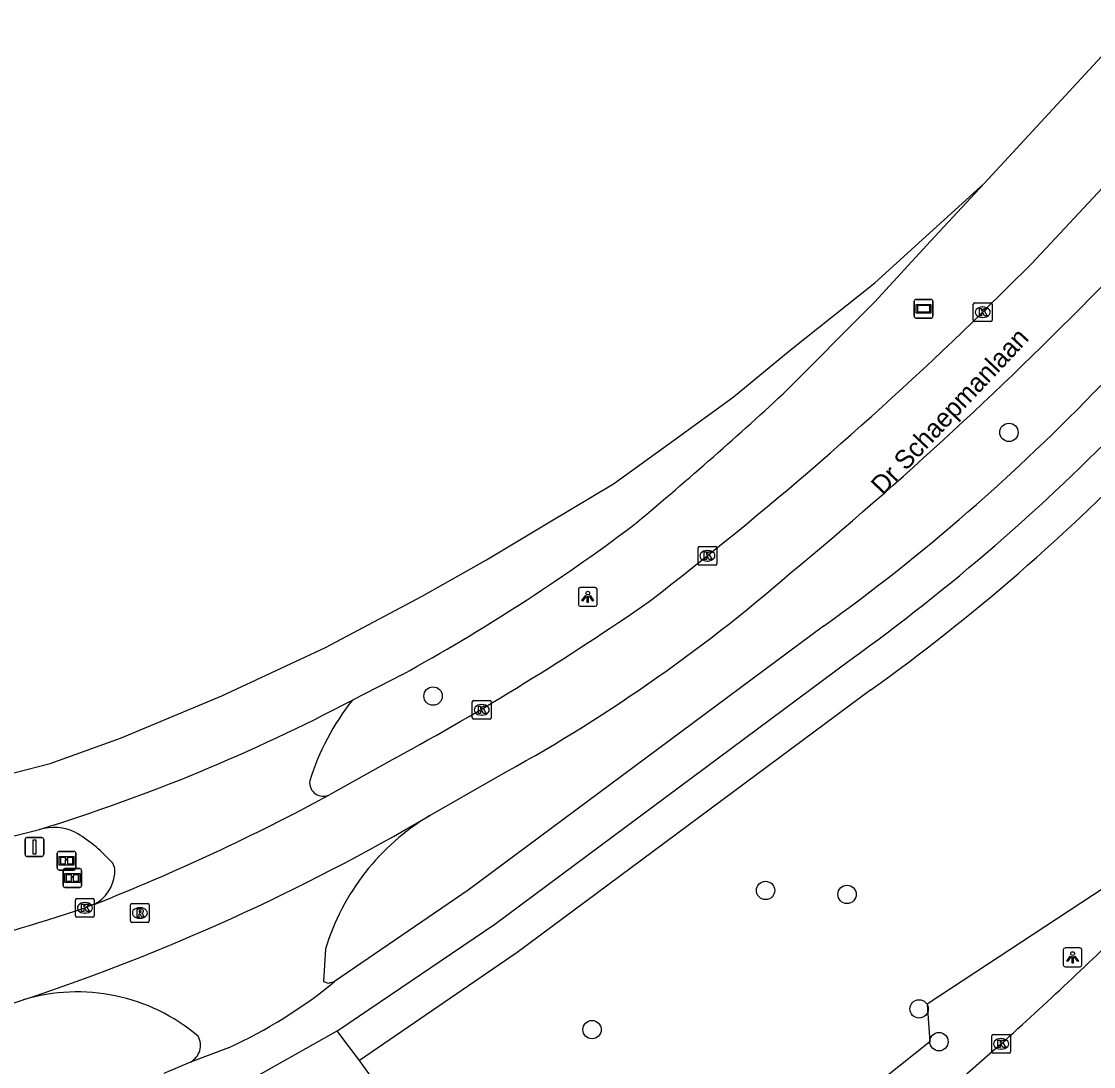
# Model space of a CAD drawing. Extents: x 161402 to 161933, y 381650 to 382313.
# Drawn here: x 161630.3 to 161687.4, y 382149.7 to 382205.3 of the extents above; entities that cross this region are included whole.
import ezdxf

# ---------------------------------------------------------------- set-up
doc = ezdxf.new("R2010")
doc.units = 0
for name, color, linetype in [('IMGEO_Boom', 7, 'Continuous'), ('IMGEO_Fietspad_open', 7, 'Continuous'), ('IMGEO_Groenvoorziening', 7, 'Continuous'), ('IMGEO_Informatiebord', 7, 'Continuous'), ('IMGEO_Kolk', 7, 'Continuous'), ('IMGEO_Lichtpunt', 7, 'Continuous'), ('IMGEO_Openbare_ruimte_label', 7, 'Continuous'), ('IMGEO_Reclamebord', 7, 'Continuous'), ('IMGEO_Rijbaan_lokaal_gesloten', 7, 'Continuous'), ('IMGEO_Rijbaan_lokaal_open', 7, 'Continuous'), ('IMGEO_Rioolput', 7, 'Continuous'), ('IMGEO_Verkeersbordpaal', 7, 'Continuous'), ('IMGEO_Voetpad_open', 7, 'Continuous')]:
    doc.layers.add(name, color=color, linetype=linetype)

msp = doc.modelspace()

# ---------------------------------------------------------------- linework, layer by layer
at = {"layer": 'IMGEO_Boom'}
for centre in [(161682.85, 382183.401), (161652.204, 382169.365), (161669.896, 382159.022), (161674.234, 382158.814), (161678.071, 382152.722), (161660.661, 382151.616), (161679.127, 382150.976)]:
    msp.add_circle(centre, 0.489, dxfattribs=at)
at = {"layer": 'IMGEO_Fietspad_open'}
for points in [[(161672.989, 382173.086), (161654.067, 382159.041), (161646.957, 382154.172)], [(161647.103, 382151.551), (161647.127, 382151.564), (161655.489, 382157.231), (161674.382, 382171.277)], [(161639.289, 382149.891), (161637.879, 382149.285)]]:
    msp.add_lwpolyline(points, dxfattribs=at)
for centre, radius, start, end in [((161610.052, 382260.44), 107.665, 305.77231, 316.20072), ((161609.744, 382261.017), 110.596, 305.76448, 315.97187)]:
    msp.add_arc(centre, radius, start, end, dxfattribs=at)
at = {"layer": 'IMGEO_Groenvoorziening'}
msp.add_lwpolyline([(161703.606, 382170.992), (161702.903, 382171.726), (161702.299, 382171.22), (161695.415, 382165.448), (161687.926, 382159.17), (161678.507, 382152.98), (161678.638, 382150.976), (161676.296, 382149.1), (161669.4, 382148.169), (161664.367, 382144.903), (161668.17, 382139.043)], dxfattribs=at)
at = {"layer": 'IMGEO_Informatiebord'}
for p, q in [((161632.199, 382160.205), (161632.199, 382161.005)), ((161632.199, 382161.005), (161632.199, 382160.205)), ((161632.299, 382161.105), (161633.089, 382161.105)), ((161633.089, 382161.105), (161632.299, 382161.105)), ((161633.189, 382161.005), (161633.189, 382160.205)), ((161633.189, 382160.205), (161633.189, 382161.005)), ((161633.089, 382160.105), (161632.299, 382160.105)), ((161632.299, 382160.105), (161633.089, 382160.105)), ((161632.508, 382159.285), (161632.508, 382160.085)), ((161632.508, 382160.085), (161632.508, 382159.285)), ((161632.608, 382160.185), (161633.398, 382160.185)), ((161633.398, 382160.185), (161632.608, 382160.185)), ((161633.498, 382160.085), (161633.498, 382159.285)), ((161633.498, 382159.285), (161633.498, 382160.085)), ((161633.398, 382159.185), (161632.608, 382159.185)), ((161632.608, 382159.185), (161633.398, 382159.185))]:
    msp.add_line(p, q, dxfattribs=at)
for points in [[(161632.3, 382160.837), (161633.088, 382160.837), (161633.088, 382160.373), (161632.3, 382160.373), (161632.3, 382160.837)], [(161632.365, 382160.772), (161632.365, 382160.438), (161632.64, 382160.438), (161632.641, 382160.651), (161632.745, 382160.652), (161632.746, 382160.438), (161633.023, 382160.438), (161633.023, 382160.772), (161632.747, 382160.772), (161632.747, 382160.692), (161632.641, 382160.692), (161632.641, 382160.772), (161632.365, 382160.772)], [(161632.609, 382159.917), (161633.397, 382159.917), (161633.397, 382159.453), (161632.609, 382159.453), (161632.609, 382159.917)], [(161632.674, 382159.852), (161632.674, 382159.518), (161632.949, 382159.518), (161632.95, 382159.731), (161633.054, 382159.732), (161633.055, 382159.518), (161633.332, 382159.518), (161633.332, 382159.852), (161633.056, 382159.852), (161633.056, 382159.772), (161632.95, 382159.772), (161632.95, 382159.852), (161632.674, 382159.852)]]:
    msp.add_lwpolyline(points, dxfattribs=at)
for centre, start, end in [((161632.299, 382161.005), 90, 180), ((161632.299, 382161.005), 90, 180), ((161633.089, 382161.005), 0, 90), ((161633.089, 382161.005), 360, 90), ((161632.299, 382160.205), 180, 270), ((161632.299, 382160.205), 180, 270), ((161632.608, 382160.085), 90, 180), ((161632.608, 382160.085), 90, 180), ((161633.089, 382160.205), 270, 0), ((161633.089, 382160.205), 270, 0), ((161633.398, 382160.085), 0, 90), ((161633.398, 382160.085), 360, 90), ((161632.608, 382159.285), 180, 270), ((161632.608, 382159.285), 180, 270), ((161633.398, 382159.285), 270, 0), ((161633.398, 382159.285), 270, 0)]:
    msp.add_arc(centre, 0.1, start, end, dxfattribs=at)
at = {"layer": 'IMGEO_Kolk'}
for p, q in [((161680.954, 382189.368), (161680.954, 382190.22)), ((161681.029, 382190.294), (161681.881, 382190.294)), ((161681.442, 382190.074), (161681.467, 382190.074)), ((161681.955, 382190.22), (161681.955, 382189.368)), ((161681.881, 382189.294), (161681.029, 382189.294)), ((161681.465, 382189.514), (161681.44, 382189.514)), ((161666.303, 382176.409), (161666.303, 382177.261)), ((161666.378, 382177.335), (161667.23, 382177.335)), ((161667.304, 382177.261), (161667.304, 382176.409)), ((161666.791, 382177.115), (161666.816, 382177.115)), ((161667.23, 382176.335), (161666.378, 382176.335)), ((161666.814, 382176.555), (161666.789, 382176.555)), ((161654.29, 382168.208), (161654.29, 382169.06)), ((161654.365, 382169.134), (161655.217, 382169.134)), ((161654.778, 382168.914), (161654.803, 382168.914)), ((161655.291, 382169.06), (161655.291, 382168.208)), ((161655.217, 382168.134), (161654.365, 382168.134)), ((161654.801, 382168.354), (161654.776, 382168.354)), ((161633.169, 382157.672), (161633.169, 382158.524)), ((161633.244, 382158.598), (161634.096, 382158.598)), ((161633.657, 382158.378), (161633.682, 382158.378)), ((161634.17, 382158.524), (161634.17, 382157.672)), ((161633.68, 382157.818), (161633.655, 382157.818)), ((161634.096, 382157.598), (161633.244, 382157.598)), ((161681.935, 382150.433), (161681.935, 382151.285)), ((161682.01, 382151.359), (161682.862, 382151.359)), ((161682.423, 382151.139), (161682.448, 382151.139)), ((161682.936, 382151.285), (161682.936, 382150.433)), ((161682.446, 382150.579), (161682.421, 382150.579)), ((161682.862, 382150.359), (161682.01, 382150.359))]:
    msp.add_line(p, q, dxfattribs=at)
for points in [[(161680.954, 382189.368), (161680.954, 382190.22)], [(161681.029, 382190.294), (161681.881, 382190.294)], [(161681.275, 382189.994), (161681.398, 382189.994), (161681.398, 382189.843), (161681.528, 382189.994), (161681.692, 382189.994), (161681.546, 382189.843), (161681.699, 382189.594), (161681.547, 382189.594), (161681.462, 382189.758), (161681.398, 382189.691), (161681.398, 382189.594), (161681.275, 382189.594), (161681.275, 382189.994)], [(161681.955, 382190.22), (161681.955, 382189.368)], [(161681.881, 382189.294), (161681.029, 382189.294)], [(161666.303, 382176.409), (161666.303, 382177.261)], [(161666.378, 382177.335), (161667.23, 382177.335)], [(161667.304, 382177.261), (161667.304, 382176.409)], [(161666.624, 382177.035), (161666.747, 382177.035), (161666.747, 382176.884), (161666.877, 382177.035), (161667.041, 382177.035), (161666.895, 382176.884), (161667.048, 382176.635), (161666.896, 382176.635), (161666.811, 382176.799), (161666.747, 382176.732), (161666.747, 382176.635), (161666.624, 382176.635), (161666.624, 382177.035)], [(161667.23, 382176.335), (161666.378, 382176.335)], [(161654.29, 382168.208), (161654.29, 382169.06)], [(161654.365, 382169.134), (161655.217, 382169.134)], [(161654.611, 382168.834), (161654.734, 382168.834), (161654.734, 382168.683), (161654.864, 382168.834), (161655.028, 382168.834), (161654.882, 382168.683), (161655.035, 382168.434), (161654.883, 382168.434), (161654.798, 382168.598), (161654.734, 382168.531), (161654.734, 382168.434), (161654.611, 382168.434), (161654.611, 382168.834)], [(161655.291, 382169.06), (161655.291, 382168.208)], [(161655.217, 382168.134), (161654.365, 382168.134)], [(161633.169, 382157.672), (161633.169, 382158.524)], [(161633.244, 382158.598), (161634.096, 382158.598)], [(161634.17, 382158.524), (161634.17, 382157.672)], [(161633.49, 382158.298), (161633.613, 382158.298), (161633.613, 382158.147), (161633.743, 382158.298), (161633.907, 382158.298), (161633.761, 382158.147), (161633.914, 382157.898), (161633.762, 382157.898), (161633.677, 382158.062), (161633.613, 382157.995), (161633.613, 382157.898), (161633.49, 382157.898), (161633.49, 382158.298)], [(161634.096, 382157.598), (161633.244, 382157.598)], [(161681.935, 382150.433), (161681.935, 382151.285)], [(161682.01, 382151.359), (161682.862, 382151.359)], [(161682.256, 382151.059), (161682.379, 382151.059), (161682.379, 382150.908), (161682.509, 382151.059), (161682.673, 382151.059), (161682.527, 382150.908), (161682.68, 382150.659), (161682.528, 382150.659), (161682.443, 382150.823), (161682.379, 382150.756), (161682.379, 382150.659), (161682.256, 382150.659), (161682.256, 382151.059)], [(161682.936, 382151.285), (161682.936, 382150.433)], [(161682.862, 382150.359), (161682.01, 382150.359)]]:
    msp.add_lwpolyline(points, dxfattribs=at)
for centre, start, end in [((161681.031, 382190.218), 91.552, 178.448), ((161681.031, 382190.218), 91.552, 178.448), ((161681.879, 382190.218), 1.552, 88.448), ((161681.879, 382190.218), 1.552, 88.448), ((161681.031, 382189.37), 181.552, 268.448), ((161681.031, 382189.37), 181.552, 268.448), ((161681.879, 382189.37), 271.552, 358.448), ((161681.879, 382189.37), 271.552, 358.448), ((161666.38, 382177.259), 91.552, 178.448), ((161666.38, 382177.259), 91.552, 178.448), ((161667.228, 382177.259), 1.552, 88.448), ((161667.228, 382177.259), 1.552, 88.448), ((161666.38, 382176.411), 181.552, 268.448), ((161666.38, 382176.411), 181.552, 268.448), ((161667.228, 382176.411), 271.552, 358.448), ((161667.228, 382176.411), 271.552, 358.448), ((161654.367, 382169.058), 91.552, 178.448), ((161654.367, 382169.058), 91.552, 178.448), ((161655.215, 382169.058), 1.552, 88.448), ((161655.215, 382169.058), 1.552, 88.448), ((161654.367, 382168.21), 181.552, 268.448), ((161654.367, 382168.21), 181.552, 268.448), ((161655.215, 382168.21), 271.552, 358.448), ((161655.215, 382168.21), 271.552, 358.448), ((161633.246, 382158.522), 91.552, 178.448), ((161633.246, 382158.522), 91.552, 178.448), ((161634.094, 382158.522), 1.552, 88.448), ((161634.094, 382158.522), 1.552, 88.448), ((161633.246, 382157.674), 181.552, 268.448), ((161633.246, 382157.674), 181.552, 268.448), ((161634.094, 382157.674), 271.552, 358.448), ((161634.094, 382157.674), 271.552, 358.448), ((161682.012, 382151.283), 91.552, 178.448), ((161682.012, 382151.283), 91.552, 178.448), ((161682.86, 382151.283), 1.552, 88.448), ((161682.86, 382151.283), 1.552, 88.448), ((161682.012, 382150.435), 181.552, 268.448), ((161682.012, 382150.435), 181.552, 268.448), ((161682.86, 382150.435), 271.552, 358.448), ((161682.86, 382150.435), 271.552, 358.448)]:
    msp.add_arc(centre, 0.0765, start, end, dxfattribs=at)
for centre, major_axis, ratio, start_param, end_param in [((161681.441, 382189.794), (-0.387, 0.002), 0.722429, 4.712389, 7.853982), ((161681.466, 382189.794), (-0.39, 0.002), 0.717154, 1.570796, 4.712389), ((161666.79, 382176.835), (-0.387, 0.002), 0.722429, 4.712389, 7.853982), ((161666.815, 382176.835), (-0.39, 0.002), 0.717154, 1.570796, 4.712389), ((161654.777, 382168.634), (-0.387, 0.002), 0.722429, 4.712389, 7.853982), ((161654.802, 382168.634), (-0.39, 0.002), 0.717154, 1.570796, 4.712389), ((161633.656, 382158.098), (-0.387, 0.002), 0.722429, 4.712389, 7.853982), ((161633.681, 382158.098), (-0.39, 0.002), 0.717154, 1.570796, 4.712389), ((161682.422, 382150.859), (-0.387, 0.002), 0.722429, 4.712389, 7.853982), ((161682.447, 382150.859), (-0.39, 0.002), 0.717154, 1.570796, 4.712389)]:
    msp.add_ellipse(centre, major_axis=major_axis, ratio=ratio, start_param=start_param, end_param=end_param, dxfattribs=at)
at = {"layer": 'IMGEO_Lichtpunt'}
for p, q in [((161659.935, 382175.05), (161659.935, 382174.243)), ((161659.935, 382175.05), (161659.935, 382174.243)), ((161660.837, 382175.145), (161660.029, 382175.145)), ((161660.837, 382175.145), (161660.029, 382175.145)), ((161660.931, 382174.243), (161660.931, 382175.05)), ((161660.931, 382174.243), (161660.931, 382175.05)), ((161660.029, 382174.149), (161660.837, 382174.149)), ((161660.029, 382174.149), (161660.837, 382174.149)), ((161685.741, 382155.866), (161685.741, 382155.059)), ((161685.741, 382155.866), (161685.741, 382155.059)), ((161686.643, 382155.961), (161685.835, 382155.961)), ((161686.643, 382155.961), (161685.835, 382155.961)), ((161686.737, 382155.059), (161686.737, 382155.866)), ((161686.737, 382155.059), (161686.737, 382155.866)), ((161685.835, 382154.965), (161686.643, 382154.965)), ((161685.835, 382154.965), (161686.643, 382154.965))]:
    msp.add_line(p, q, dxfattribs=at)
for points in [[(161660.309, 382174.714), (161660.348, 382174.686), (161660.16, 382174.424), (161660.122, 382174.451), (161660.309, 382174.714)], [(161660.411, 382174.666), (161660.458, 382174.666), (161660.458, 382174.344), (161660.411, 382174.344), (161660.411, 382174.666)], [(161660.521, 382174.686), (161660.559, 382174.713), (161660.746, 382174.451), (161660.707, 382174.423), (161660.521, 382174.686)], [(161686.115, 382155.53), (161686.154, 382155.502), (161685.966, 382155.24), (161685.928, 382155.267), (161686.115, 382155.53)], [(161686.327, 382155.502), (161686.365, 382155.529), (161686.552, 382155.267), (161686.513, 382155.239), (161686.327, 382155.502)], [(161686.217, 382155.482), (161686.264, 382155.482), (161686.264, 382155.16), (161686.217, 382155.16), (161686.217, 382155.482)]]:
    msp.add_lwpolyline(points, dxfattribs=at)
for centre in [(161660.434, 382174.848), (161686.24, 382155.664)]:
    msp.add_circle(centre, 0.0994, dxfattribs=at)
for centre, start, end in [((161660.029, 382175.05), 90, 180), ((161660.029, 382175.05), 90, 180), ((161660.837, 382175.05), 0, 90), ((161660.837, 382175.05), 0, 90), ((161660.029, 382174.243), 180, 270), ((161660.029, 382174.243), 180, 270), ((161660.837, 382174.243), 270, 0), ((161660.837, 382174.243), 270, 360), ((161685.835, 382155.866), 90, 180), ((161685.835, 382155.866), 90, 180), ((161686.643, 382155.866), 0, 90), ((161686.643, 382155.866), 0, 90), ((161685.835, 382155.059), 180, 270), ((161685.835, 382155.059), 180, 270), ((161686.643, 382155.059), 270, 0), ((161686.643, 382155.059), 270, 360)]:
    msp.add_arc(centre, 0.0946, start, end, dxfattribs=at)
at = {"layer": 'IMGEO_Reclamebord'}
for p, q in [((161677.81, 382189.579), (161677.81, 382190.379)), ((161677.81, 382190.379), (161677.81, 382189.579)), ((161677.91, 382190.479), (161678.7, 382190.479)), ((161678.7, 382190.479), (161677.91, 382190.479)), ((161678.8, 382190.379), (161678.8, 382189.579)), ((161678.8, 382189.579), (161678.8, 382190.379)), ((161678.7, 382189.479), (161677.91, 382189.479)), ((161677.91, 382189.479), (161678.7, 382189.479))]:
    msp.add_line(p, q, dxfattribs=at)
for points in [[(161677.911, 382190.211), (161678.699, 382190.211), (161678.699, 382189.747), (161677.911, 382189.747), (161677.911, 382190.211)], [(161677.976, 382190.146), (161677.976, 382189.812), (161678.634, 382189.812), (161678.634, 382190.146), (161677.976, 382190.146)]]:
    msp.add_lwpolyline(points, dxfattribs=at)
for centre, start, end in [((161677.91, 382190.379), 90, 180), ((161677.91, 382190.379), 90, 180), ((161678.7, 382190.379), 0, 90), ((161678.7, 382190.379), 360, 90), ((161677.91, 382189.579), 180, 270), ((161677.91, 382189.579), 180, 270), ((161678.7, 382189.579), 270, 0), ((161678.7, 382189.579), 270, 0)]:
    msp.add_arc(centre, 0.1, start, end, dxfattribs=at)
at = {"layer": 'IMGEO_Rijbaan_lokaal_gesloten'}
for points in [[(161681.527, 382196.651), (161689.496, 382205.269)], [(161693.624, 382202.616), (161684.055, 382192.367), (161681.452, 382189.793)], [(161623.784, 382163.77), (161624.938, 382164.015), (161626.127, 382164.318), (161628.228, 382164.854), (161631.83, 382165.772), (161635.569, 382167.127), (161640.958, 382169.372), (161646.471, 382171.949), (161651.617, 382174.687), (161655.041, 382176.626), (161658.42, 382178.643), (161661.8, 382180.659), (161664.99, 382182.963), (161668.181, 382185.266), (161671.208, 382187.781), (161675.716, 382191.356), (161681.527, 382196.651)], [(161681.527, 382196.651), (161678.676, 382193.568), (161675.69, 382190.338), (161670.839, 382185.46)], [(161650.566, 382170.516), (161647.909, 382169.155)], [(161650.189, 382166.07), (161646.692, 382164.118)], [(161652.03, 382163.012), (161655.565, 382165.041)], [(161634.171, 382158.285), (161633.67, 382158.098)], [(161626.494, 382152.087), (161629.901, 382153.042), (161630.394, 382153.204)], [(161641.929, 382148.646), (161647.103, 382151.551)], [(161648.28, 382149.971), (161647.285, 382151.292), (161647.103, 382151.551)], [(161682.436, 382150.859), (161677.822, 382146.79), (161674.829, 382144.218)], [(161649.489, 382148.283), (161648.519, 382149.653), (161648.28, 382149.971)]]:
    msp.add_lwpolyline(points, dxfattribs=at)
for centre, radius, start, end in [((161535.498, 382339.885), 212.859, 309.61126, 315.82773), ((161541.345, 382333.441), 200.661, 307.57252, 314.28499), ((161533.926, 382333.423), 201.589, 309.7406, 312.77852), ((161600.847, 382261.015), 103.257, 298.7838, 306.87243), ((161613.695, 382242.064), 87.667, 298.52876, 311.00082), ((161580.781, 382293.765), 145.339, 298.52599, 304.78691), ((161602.481, 382255.416), 97.492, 287.16795, 297.77288), ((161593.034, 382262.943), 112.453, 291.45766, 298.49995), ((161594.959, 382260.14), 112.654, 288.33348, 300.43786), ((161602.174, 382276.728), 118.097, 280.86297, 284.25685), ((161588.568, 382295.063), 144.2, 284.94839, 288.22657), ((161516.254, 382334.874), 247.948, 312.0848, 314.31888)]:
    msp.add_arc(centre, radius, start, end, dxfattribs=at)
at = {"layer": 'IMGEO_Rijbaan_lokaal_open'}
for points in [[(161646.478, 382155.909), (161646.374, 382154.17), (161646.623, 382154.084), (161646.957, 382154.172)], [(161641.314, 382150.656), (161639.289, 382149.891)]]:
    msp.add_lwpolyline(points, dxfattribs=at)
for centre, radius, start, end in [((161658.535, 382160.777), 13.531, 141.748, 162.444), ((161646.362, 382164.772), 0.733, 173.1846, 296.8023), ((161658.433, 382152.286), 12.492, 120.8345, 163.1402), ((161632.01, 382159.68), 2.695, 64.3723, 106.2092), ((161628.863, 382154.883), 8.416, 43.0102, 59.171), ((161634.529, 382160.062), 0.745, 347.5482, 49.0361), ((161633.218, 382160.097), 2.047, 297.7349, 354.5094), ((161630.931, 382173.607), 25.19, 294.3425, 309.5093), ((161633.262, 382143.66), 9.966, 49.7943, 106.7247), ((161638.82, 382150.779), 1.004, 297.8571, 29.3549)]:
    msp.add_arc(centre, radius, start, end, dxfattribs=at)
at = {"layer": 'IMGEO_Rioolput'}
for p, q in [((161636.096, 382157.398), (161636.096, 382158.25)), ((161636.171, 382158.324), (161637.023, 382158.324)), ((161636.584, 382158.104), (161636.609, 382158.104)), ((161637.097, 382158.25), (161637.097, 382157.398)), ((161637.023, 382157.324), (161636.171, 382157.324)), ((161636.607, 382157.544), (161636.582, 382157.544))]:
    msp.add_line(p, q, dxfattribs=at)
for points in [[(161636.096, 382157.398), (161636.096, 382158.25)], [(161636.171, 382158.324), (161637.023, 382158.324)], [(161636.685, 382158.022), (161636.433, 382158.024), (161636.433, 382157.624)], [(161636.433, 382157.624), (161636.557, 382157.624), (161636.557, 382157.786), (161636.568, 382157.786)], [(161636.611, 382157.943), (161636.557, 382157.943), (161636.557, 382157.862)], [(161636.557, 382157.862), (161636.609, 382157.862)], [(161637.097, 382158.25), (161637.097, 382157.398)], [(161637.023, 382157.324), (161636.171, 382157.324)], [(161636.615, 382157.757), (161636.686, 382157.624), (161636.826, 382157.624), (161636.761, 382157.75)]]:
    msp.add_lwpolyline(points, dxfattribs=at)
for centre, radius, start, end in [((161636.173, 382158.248), 0.0765, 91.552, 178.448), ((161636.173, 382158.248), 0.0765, 91.552, 178.448), ((161636.567, 382157.733), 0.0533, 26.0293, 88.6989), ((161636.593, 382158.051), 0.19, 274.7715, 282.9687), ((161636.617, 382157.847), 0.0964, 77.0061, 93.1865), ((161636.631, 382157.904), 0.0378, 276.6634, 79.6772), ((161636.684, 382157.912), 0.109, 350.3612, 89.416), ((161636.682, 382157.912), 0.112, 277.5842, 350.9817), ((161636.666, 382157.697), 0.108, 29.5134, 73.7905), ((161637.021, 382158.248), 0.0765, 1.552, 88.448), ((161637.021, 382158.248), 0.0765, 1.552, 88.448), ((161636.173, 382157.4), 0.0765, 181.552, 268.448), ((161636.173, 382157.4), 0.0765, 181.552, 268.448), ((161637.021, 382157.4), 0.0765, 271.552, 358.448), ((161637.021, 382157.4), 0.0765, 271.552, 358.448)]:
    msp.add_arc(centre, radius, start, end, dxfattribs=at)
for centre, major_axis, ratio, start_param, end_param in [((161636.583, 382157.824), (-0.387, 0.002), 0.722429, 4.712389, 7.853982), ((161636.608, 382157.824), (-0.39, 0.002), 0.717154, 1.570796, 4.712389)]:
    msp.add_ellipse(centre, major_axis=major_axis, ratio=ratio, start_param=start_param, end_param=end_param, dxfattribs=at)
at = {"layer": 'IMGEO_Verkeersbordpaal'}
for p, q in [((161630.589, 382161.838), (161631.379, 382161.838)), ((161631.379, 382161.838), (161630.589, 382161.838)), ((161630.489, 382160.938), (161630.489, 382161.738)), ((161630.489, 382161.738), (161630.489, 382160.938)), ((161631.479, 382161.738), (161631.479, 382160.938)), ((161631.479, 382160.938), (161631.479, 382161.738)), ((161631.379, 382160.838), (161630.589, 382160.838)), ((161630.589, 382160.838), (161631.379, 382160.838))]:
    msp.add_line(p, q, dxfattribs=at)
msp.add_lwpolyline([(161630.909, 382161.713), (161631.059, 382161.713), (161631.059, 382160.963), (161630.909, 382160.963), (161630.909, 382161.713)], dxfattribs=at)
for centre, start, end in [((161630.589, 382161.738), 90, 180), ((161630.589, 382161.738), 90, 180), ((161631.379, 382161.738), 0, 90), ((161631.379, 382161.738), 360, 90), ((161630.589, 382160.938), 180, 270), ((161630.589, 382160.938), 180, 270), ((161631.379, 382160.938), 270, 0), ((161631.379, 382160.938), 270, 0)]:
    msp.add_arc(centre, 0.1, start, end, dxfattribs=at)
at = {"layer": 'IMGEO_Voetpad_open'}
msp.add_lwpolyline([(161675.495, 382169.693), (161656.68, 382155.718), (161648.28, 382149.971)], dxfattribs=at)
msp.add_arc((161611.861, 382258.34), 109.122, 305.67199, 316.21436, dxfattribs=at)

# ---------------------------------------------------------------- texts
at = {"layer": 'IMGEO_Openbare_ruimte_label'}
msp.add_text('Dr Schaepmanlaan', height=1, rotation=46.8241, dxfattribs=at).set_placement((161676.14, 382180.016))

doc.saveas('drawing.dxf')
